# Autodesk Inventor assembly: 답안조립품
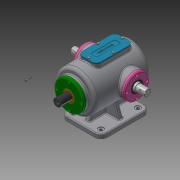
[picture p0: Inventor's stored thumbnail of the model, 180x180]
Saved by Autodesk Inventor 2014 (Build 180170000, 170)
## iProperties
Created: 2021-11
Part Number: 답안조립품
Document SubType Name: Assembly
Designer: kb542-12
Author: kb542-12
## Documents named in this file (14)
- C:\Users\kb542-12\Desktop\711106V1003\답안조립품.iam
- C:\Users\kb542-12\Desktop\711106V1003\답안본체.ipt
- C:\Users\kb542-12\Desktop\711106V1003\베어링 6205.ipt
- 베어링 6205.ipt
- C:\Users\kb542-12\Desktop\711106V1003\볼트 M4x0.7.ipt
- C:\Users\kb542-12\Desktop\711106V1003\부시.ipt
- C:\Users\kb542-12\Desktop\711106V1003\상부커버.ipt
- C:\Users\kb542-12\Desktop\711106V1003\슬라이드 커버.ipt
- C:\Users\kb542-12\Desktop\711106V1003\슬라이드.ipt
- C:\Users\kb542-12\Desktop\711106V1003\오일실.ipt
- 오일실.ipt
- C:\Users\kb542-12\Desktop\711106V1003\육각머리볼트 M4.ipt
- C:\Users\kb542-12\Desktop\711106V1003\축 커버.ipt
- C:\Users\kb542-12\Desktop\711106V1003\편심축.ipt
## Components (1 placed, 1 different names)
1. M4x0.7:1
